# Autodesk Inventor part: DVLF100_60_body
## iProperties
Created: 2010-03
Part Number: DVLF100_60_body
Document SubType Name: Modeling
Designer: TB
Mass: 2266.53 g
Surface Area: 2607.47 cm^2
Volume: 2266.53 cm^3
Density: 1 g/cm^3
Author: TB
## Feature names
1. Kropp [Revolution]
2. Chamfer
3. Extrusion2
4. Hole1
5. Revolution2
6. Hole2
7. Fillet1
8. Extrusion3
9. Hole3
